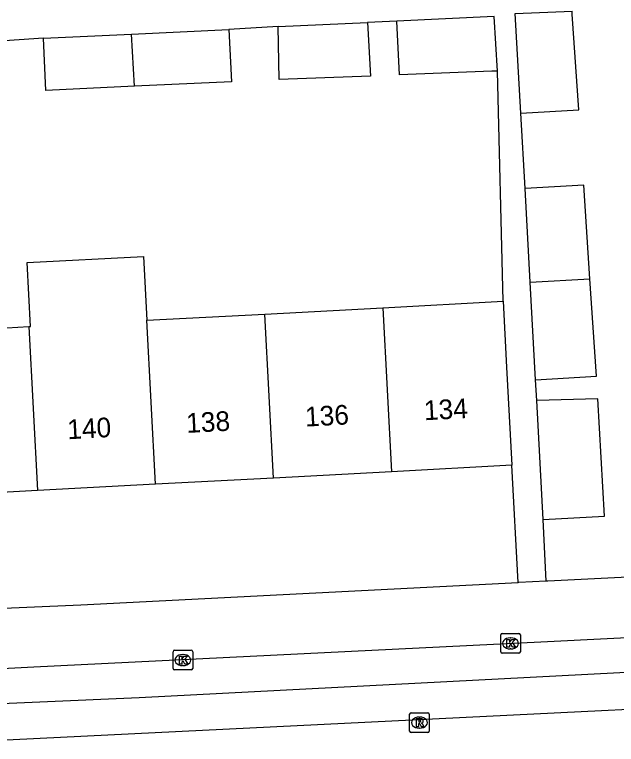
# Model space of a CAD drawing. Extents: x 160557 to 161245, y 385330 to 386505.
# Drawn here: x 160873.18 to 160903.75, y 385334.44 to 385371.51 of the extents above; entities that cross this region are included whole.
import ezdxf

# ---------------------------------------------------------------- set-up
doc = ezdxf.new("R2010")
doc.units = 0
for name, color, linetype in [('IMGEO_Fietspad_gesloten', 7, 'Continuous'), ('IMGEO_Kolk', 7, 'Continuous'), ('IMGEO_Pand', 7, 'Continuous'), ('IMGEO_Pand_nummerreeks', 7, 'Continuous'), ('IMGEO_Rijbaan_lokaal_gesloten', 7, 'Continuous'), ('IMGEO_Rioolput', 7, 'Continuous'), ('IMGEO_Voetpad_open', 7, 'Continuous')]:
    doc.layers.add(name, color=color, linetype=linetype)

msp = doc.modelspace()

# ---------------------------------------------------------------- linework, layer by layer
at = {"layer": 'IMGEO_Fietspad_gesloten'}
msp.add_lwpolyline([(160923.045, 385339.071), (160906.536, 385338.204), (160879.509, 385336.797), (160869.015, 385336.349)], dxfattribs=at)
at = {"layer": 'IMGEO_Kolk'}
for p, q in [((160897.949, 385340.07), (160898.801, 385340.07)), ((160897.874, 385339.144), (160897.874, 385339.996)), ((160898.362, 385339.85), (160898.387, 385339.85)), ((160898.875, 385339.996), (160898.875, 385339.144)), ((160881.228, 385338.296), (160881.228, 385339.148)), ((160881.303, 385339.222), (160882.155, 385339.222)), ((160881.716, 385339.002), (160881.741, 385339.002)), ((160882.229, 385339.148), (160882.229, 385338.296)), ((160898.801, 385339.07), (160897.949, 385339.07)), ((160898.385, 385339.29), (160898.36, 385339.29)), ((160882.155, 385338.222), (160881.303, 385338.222)), ((160881.739, 385338.442), (160881.714, 385338.442))]:
    msp.add_line(p, q, dxfattribs=at)
for points in [[(160897.949, 385340.07), (160898.801, 385340.07)], [(160897.874, 385339.144), (160897.874, 385339.996)], [(160898.195, 385339.77), (160898.318, 385339.77), (160898.318, 385339.619), (160898.448, 385339.77), (160898.612, 385339.77), (160898.466, 385339.619), (160898.619, 385339.37), (160898.467, 385339.37), (160898.382, 385339.534), (160898.318, 385339.467), (160898.318, 385339.37), (160898.195, 385339.37), (160898.195, 385339.77)], [(160898.875, 385339.996), (160898.875, 385339.144)], [(160881.228, 385338.296), (160881.228, 385339.148)], [(160881.303, 385339.222), (160882.155, 385339.222)], [(160882.229, 385339.148), (160882.229, 385338.296)], [(160898.801, 385339.07), (160897.949, 385339.07)], [(160881.549, 385338.922), (160881.672, 385338.922), (160881.672, 385338.771), (160881.802, 385338.922), (160881.966, 385338.922), (160881.82, 385338.771), (160881.973, 385338.522), (160881.821, 385338.522), (160881.736, 385338.686), (160881.672, 385338.619), (160881.672, 385338.522), (160881.549, 385338.522), (160881.549, 385338.922)], [(160882.155, 385338.222), (160881.303, 385338.222)]]:
    msp.add_lwpolyline(points, dxfattribs=at)
for centre, start, end in [((160897.951, 385339.994), 91.552, 178.448), ((160897.951, 385339.994), 91.552, 178.448), ((160898.799, 385339.994), 1.552, 88.448), ((160898.799, 385339.994), 1.552, 88.448), ((160881.305, 385339.146), 91.552, 178.448), ((160881.305, 385339.146), 91.552, 178.448), ((160882.153, 385339.146), 1.552, 88.448), ((160882.153, 385339.146), 1.552, 88.448), ((160897.951, 385339.146), 181.552, 268.448), ((160897.951, 385339.146), 181.552, 268.448), ((160898.799, 385339.146), 271.552, 358.448), ((160898.799, 385339.146), 271.552, 358.448), ((160881.305, 385338.298), 181.552, 268.448), ((160881.305, 385338.298), 181.552, 268.448), ((160882.153, 385338.298), 271.552, 358.448), ((160882.153, 385338.298), 271.552, 358.448)]:
    msp.add_arc(centre, 0.0765, start, end, dxfattribs=at)
for centre, major_axis, ratio, start_param, end_param in [((160898.361, 385339.57), (-0.387, 0.002), 0.722429, 4.712389, 7.853982), ((160898.386, 385339.57), (-0.39, 0.002), 0.717154, 1.570796, 4.712389), ((160881.715, 385338.722), (-0.387, 0.002), 0.722429, 4.712389, 7.853982), ((160881.74, 385338.722), (-0.39, 0.002), 0.717154, 1.570796, 4.712389)]:
    msp.add_ellipse(centre, major_axis=major_axis, ratio=ratio, start_param=start_param, end_param=end_param, dxfattribs=at)
at = {"layer": 'IMGEO_Pand'}
for points in [[(160898.897, 385366.5), (160898.616, 385371.559), (160901.502, 385371.69)], [(160898.897, 385366.5), (160901.838, 385366.669), (160901.512, 385371.536), (160901.502, 385371.69)], [(160897.711, 385368.642), (160897.539, 385371.415), (160892.603, 385371.183)], [(160891.112, 385371.113), (160891.257, 385368.387), (160886.622, 385368.205), (160886.563, 385370.9)], [(160886.563, 385370.9), (160891.112, 385371.113)], [(160897.711, 385368.642), (160897.419, 385368.63), (160892.731, 385368.445), (160892.603, 385371.183)], [(160874.65, 385370.313), (160879.123, 385370.521)], [(160879.123, 385370.521), (160884.068, 385370.75)], [(160879.264, 385367.867), (160879.123, 385370.521)], [(160884.068, 385370.75), (160884.191, 385368.096), (160879.264, 385367.867)], [(160879.264, 385367.867), (160874.773, 385367.659), (160874.65, 385370.313)], [(160902.409, 385358.084), (160902.092, 385362.843), (160899.11, 385362.675)], [(160899.374, 385357.92), (160899.11, 385362.675)], [(160873.906, 385355.66), (160873.986, 385355.664), (160873.813, 385358.913), (160879.724, 385359.228), (160879.897, 385355.979)], [(160899.374, 385357.92), (160902.409, 385358.084)], [(160899.65, 385352.956), (160899.374, 385357.92)], [(160899.65, 385352.956), (160902.739, 385353.145), (160902.409, 385358.084)], [(160891.88, 385356.618), (160897.997, 385356.944)], [(160897.997, 385356.944), (160898.175, 385353.607), (160898.441, 385348.614)], [(160885.889, 385356.299), (160891.88, 385356.618)], [(160891.88, 385356.618), (160892.324, 385348.288)], [(160879.897, 385355.979), (160885.889, 385356.299)], [(160886.333, 385347.969), (160885.889, 385356.299)], [(160874.35, 385347.33), (160868.237, 385347.004), (160867.793, 385355.334), (160872.786, 385355.6), (160873.906, 385355.66)], [(160873.906, 385355.66), (160874.35, 385347.33)], [(160880.341, 385347.649), (160879.897, 385355.979)], [(160900.026, 385345.864), (160903.149, 385346.031), (160902.817, 385351.984), (160899.708, 385351.905)], [(160900.026, 385345.864), (160899.708, 385351.905)], [(160898.441, 385348.614), (160892.324, 385348.288)], [(160892.324, 385348.288), (160886.333, 385347.969)], [(160886.333, 385347.969), (160880.341, 385347.649)], [(160880.341, 385347.649), (160874.35, 385347.33)]]:
    msp.add_lwpolyline(points, dxfattribs=at)
at = {"layer": 'IMGEO_Rijbaan_lokaal_gesloten'}
msp.add_lwpolyline([(161179.212, 385352.808), (161177.568, 385352.385), (161171.027, 385350.994), (161157.592, 385349.093), (161141.871, 385348.183), (161034.402, 385342.87), (160939.068, 385337.926), (160868.279, 385334.438)], dxfattribs=at)
at = {"layer": 'IMGEO_Rioolput'}
for p, q in [((160893.322, 385336.044), (160894.174, 385336.044)), ((160893.247, 385335.118), (160893.247, 385335.97)), ((160893.735, 385335.824), (160893.76, 385335.824)), ((160894.248, 385335.97), (160894.248, 385335.118)), ((160893.758, 385335.264), (160893.733, 385335.264)), ((160894.174, 385335.044), (160893.322, 385335.044))]:
    msp.add_line(p, q, dxfattribs=at)
for points in [[(160893.322, 385336.044), (160894.174, 385336.044)], [(160893.247, 385335.118), (160893.247, 385335.97)], [(160893.836, 385335.742), (160893.584, 385335.744), (160893.584, 385335.344)], [(160893.762, 385335.663), (160893.708, 385335.663), (160893.708, 385335.582)], [(160894.248, 385335.97), (160894.248, 385335.118)], [(160893.584, 385335.344), (160893.708, 385335.344), (160893.708, 385335.506), (160893.719, 385335.506)], [(160893.708, 385335.582), (160893.76, 385335.582)], [(160893.766, 385335.477), (160893.837, 385335.344), (160893.977, 385335.344), (160893.912, 385335.47)], [(160894.174, 385335.044), (160893.322, 385335.044)]]:
    msp.add_lwpolyline(points, dxfattribs=at)
for centre, radius, start, end in [((160893.324, 385335.968), 0.0765, 91.552, 178.448), ((160893.324, 385335.968), 0.0765, 91.552, 178.448), ((160894.172, 385335.968), 0.0765, 1.552, 88.448), ((160894.172, 385335.968), 0.0765, 1.552, 88.448), ((160893.768, 385335.567), 0.0964, 77.0061, 93.1865), ((160893.782, 385335.624), 0.0378, 276.6634, 79.6772), ((160893.835, 385335.632), 0.109, 350.3612, 89.416), ((160893.718, 385335.453), 0.0533, 26.0293, 88.6989), ((160893.744, 385335.771), 0.19, 274.7715, 282.9687), ((160893.833, 385335.632), 0.112, 277.5842, 350.9817), ((160893.817, 385335.417), 0.108, 29.5134, 73.7905), ((160893.324, 385335.12), 0.0765, 181.552, 268.448), ((160893.324, 385335.12), 0.0765, 181.552, 268.448), ((160894.172, 385335.12), 0.0765, 271.552, 358.448), ((160894.172, 385335.12), 0.0765, 271.552, 358.448)]:
    msp.add_arc(centre, radius, start, end, dxfattribs=at)
for centre, major_axis, ratio, start_param, end_param in [((160893.734, 385335.544), (-0.387, 0.002), 0.722429, 4.712389, 7.853982), ((160893.759, 385335.544), (-0.39, 0.002), 0.717154, 1.570796, 4.712389)]:
    msp.add_ellipse(centre, major_axis=major_axis, ratio=ratio, start_param=start_param, end_param=end_param, dxfattribs=at)
at = {"layer": 'IMGEO_Voetpad_open'}
for points in [[(160886.563, 385370.9), (160884.068, 385370.75)], [(160892.603, 385371.183), (160891.112, 385371.113)], [(160874.65, 385370.313), (160870.918, 385370.055)], [(160897.997, 385356.944), (160897.711, 385368.642)], [(160899.11, 385362.675), (160898.897, 385366.5)], [(160899.708, 385351.905), (160899.65, 385352.956)], [(160898.758, 385342.66), (160898.441, 385348.614)], [(160900.191, 385342.73), (160900.026, 385345.864)], [(160919.294, 385343.663), (160904.681, 385342.949), (160900.274, 385342.734), (160900.191, 385342.73)], [(160864.928, 385340.852), (160867.914, 385340.98), (160867.905, 385341.148), (160876.541, 385341.524), (160898.758, 385342.66)], [(160900.191, 385342.73), (160898.797, 385342.662), (160898.758, 385342.66)], [(160872.546, 385338.296), (160874.155, 385338.382), (160899.913, 385339.647), (160903.631, 385339.837), (160921.942, 385340.769)]]:
    msp.add_lwpolyline(points, dxfattribs=at)

# ---------------------------------------------------------------- texts
at = {"layer": 'IMGEO_Pand_nummerreeks'}
for s, rotation, p in [('134', 3.0512, (160894, 385350.901)), ('136', 3.0512, (160887.959, 385350.579)), ('138', 3.0512, (160881.923, 385350.258)), ('140', 3.0539, (160875.882, 385349.936))]:
    msp.add_text(s, height=1, rotation=rotation, dxfattribs=at).set_placement(p)

doc.saveas('drawing.dxf')
